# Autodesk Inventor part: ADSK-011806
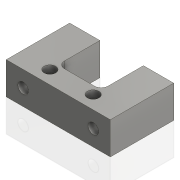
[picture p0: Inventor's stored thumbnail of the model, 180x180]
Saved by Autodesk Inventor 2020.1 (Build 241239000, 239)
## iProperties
Created: 1999-12
Part Number: ADSK-011806
Material: Aluminum
Description: SLIDE BODY_SD22
Document SubType Name: Modeling
Designer: glanglot
Density: 2.71 g/cm^3
Appearance: Steel
Mass: 319.117 g
Surface Area: 257.1 cm^2
Volume: 117.755 cm^3
Control State: 0
Master: False
Checked Out: False
Shininess: 0.0
Length Units: 11269
Angle Units: 11279
Time Units: 11290
Mass Units: 11283
Length Display Precision: 3
Angle Display Precision: 2
Compacted: True
Dimensions: 98,5x30,5x60 mm
Mass: 0,319 kg
Density: 0.0
Volumn: 0.0
Area: 0.0
PropertySet Name: Model Information
Author: glanglot
Revision Number: -
Title: SLIDE BODY_SD22
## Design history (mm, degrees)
node "Solide1"
  node "Extrusion1" dims "d2" = 60, "d3" = 0
  node "Hole1" dims "d7" = 10, "d8" = 9.525, "d9" = 6.35, "d10" = 60 deg, "d11" = 19.05, "d12" = 118 deg, "d41" = 6
  node "Hole2" dims "d16" = 6.6, "d17" = 11, "d18" = 6.8, "d19" = 60 deg, "d20" = 19.05, "d21" = 118 deg, "d40" = 6
  node "Hole3" dims "d27" = 3.683, "d28" = 15.875, "d29" = 11.176, "d30" = 60 deg, "d31" = 9.398, "d32" = 118 deg
  node "Extrusion2" dims "d37" = 86.106, "d38" = 0
  node "Fillet1" dims "d39" = 6.35
sketch "Sketch1"
  geometry: L1 (0, 30.5)-(98.5, 30.5); L2 (98.5, 30.5)-(98.5, 0); L3 (98.5, 0)-(0, 0); L4 (0, 0)-(0, 30.5); 1 further point
  constraints: 8 end point, 2 parallel, 1 coincident, 1 horizontal, 1 perpendicular
  dimensions: "d0" = 30.5 distance of L3.end L1.start; "d1" = 98.5 distance of L2.end L3.end
sketch "Sketch2"
  geometry: L1 (0, 30.5)-(98.5, 30.5) reference; L2 (0, 0)-(0, 30.5) reference; L3 (82.5, 15.25)-(16, 15.25); 3 further points
  constraints: 3 midpoint, 2 end point, 2 horizontal alignment, 1 horizontal, 1 vertical alignment
  dimensions: "d5" = 66.5 distance of L3.start L3.end
sketch "Sketch3"
  geometry: L1 (0, -60)-(98.5, -60) reference; L2 (28.75, -47.5)-(69.75, -47.5); 2 further points
  constraints: 2 end point, 2 midpoint, 1 horizontal, 1 horizontal alignment, 1 vertical alignment
  dimensions: "d13" = 12.5 distance from line of L2.start L1; "d15" = 41 distance of L2.end L2.start
sketch "Sketch4"
  geometry: L1 (98.5, 60)-(0, 60) reference; L2 (0, 0)-(0, 60) reference; L3 (92.75, 12.5)-(5.75, 12.5); L4 (5.75, 12.5)-(5.75, 47.5); L5 (5.75, 47.5)-(92.75, 47.5); L6 (92.75, 47.5)-(92.75, 12.5); 6 further points
  constraints: 8 end point, 4 midpoint, 3 horizontal alignment, 3 vertical alignment, 2 parallel, 1 horizontal, 1 perpendicular
  dimensions: "d23" = 35 distance of point (5.75, 12.5) L4.end; "d42" = 87 distance of L3.start L3.end
node "Corps solides"
node "Corps surfaciques"
sketch "Sketch5"
  geometry: L1 (0, -60)-(98.5, -60) reference; L2 (98.5, 0)-(0, 0) reference; L3 (0, 0)-(0, -60) reference; L4 (28.575, 0)-(28.575, -39.934); L5 (28.575, -39.934)-(69.85, -39.934); L6 (69.85, -39.934)-(69.85, 0)
  constraints: 6 end point, 2 perpendicular, 2 point on line, 1 parallel
  dimensions: "d33" = 20.066 distance between parallel lines of L5 L1; "d34" = 28.575 distance between parallel lines of L4 L3; "d36" = 41.275 distance between parallel lines of L6 L4
